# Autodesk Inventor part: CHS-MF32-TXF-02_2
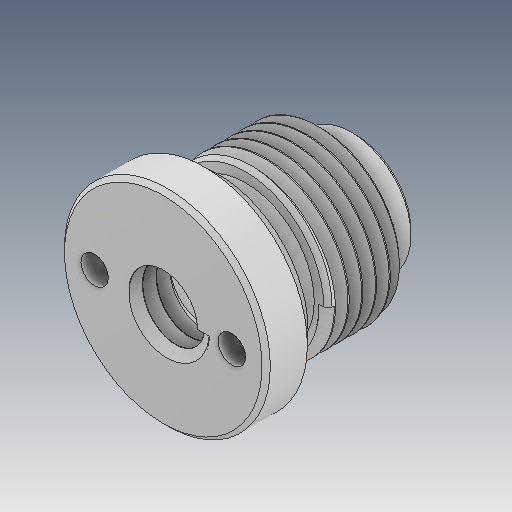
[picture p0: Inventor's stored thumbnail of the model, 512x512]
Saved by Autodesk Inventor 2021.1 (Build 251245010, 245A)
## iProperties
Created: 2021-05
Part Number: CHS-MF32-TXF-02_2
Material: Ogólny
Document SubType Name: Modeling
Designer: user
Density: 1 g/cm^3
Appearance: Domyślna
Author: user
Revision Number: ÈÎºÎ
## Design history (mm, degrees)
feature "ÊäÈë1"
node "Bryła1"
